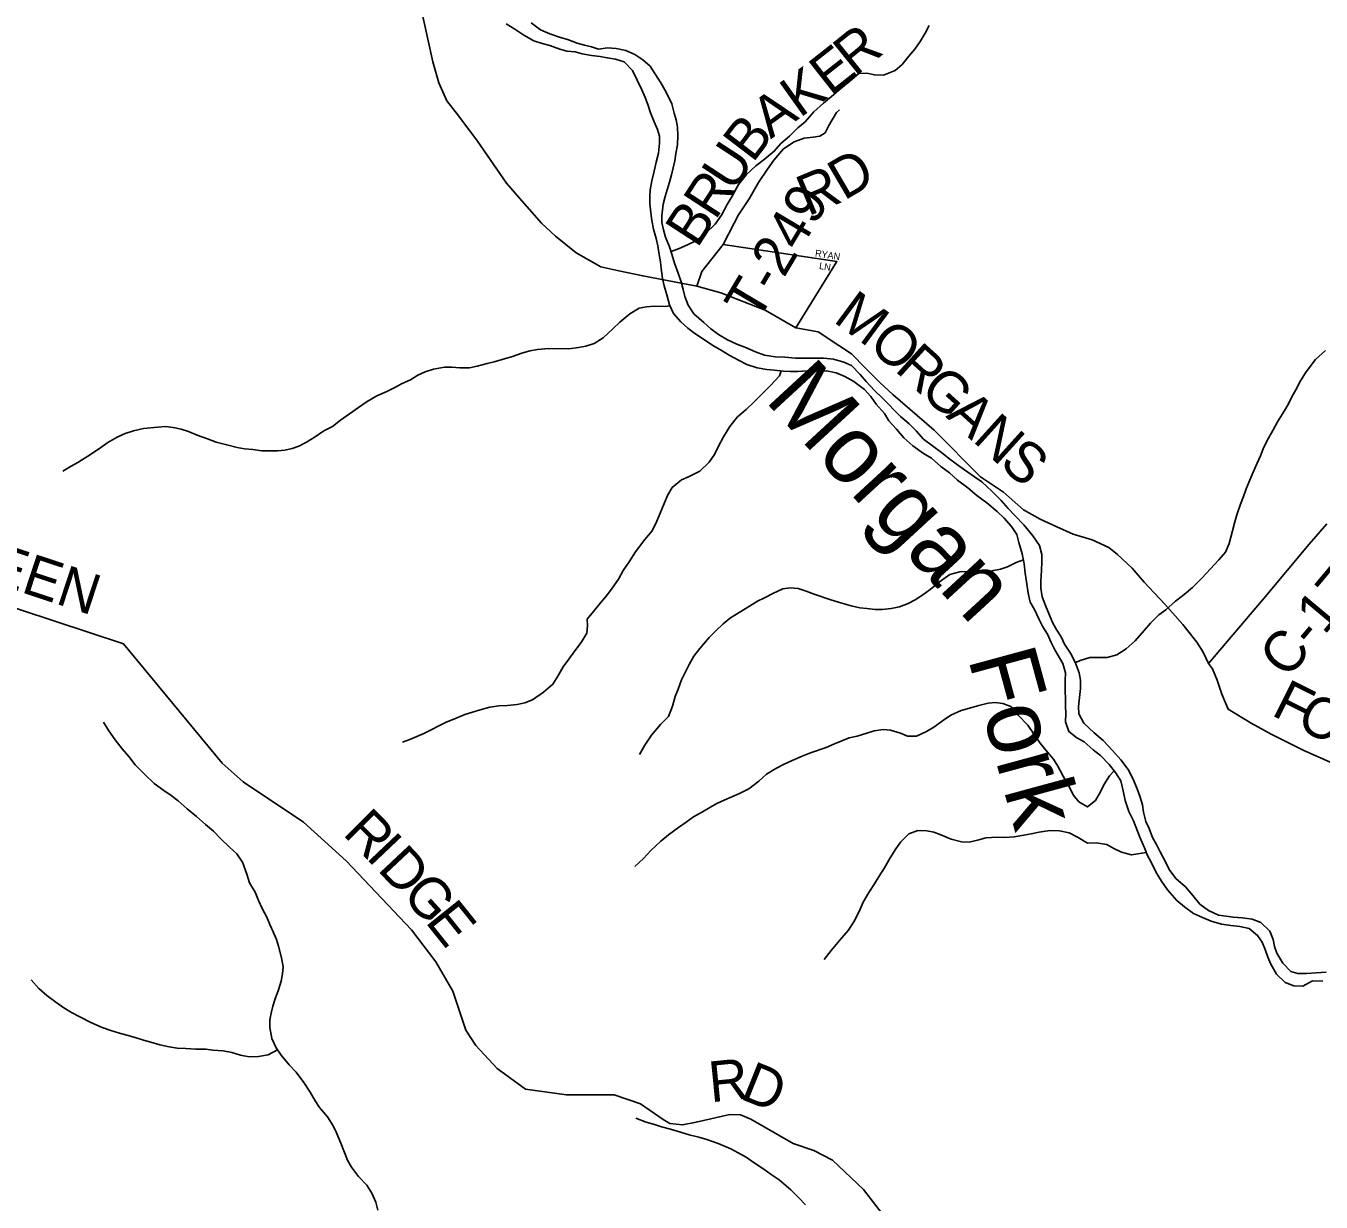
# Model space of a CAD drawing. Extents: x 1578669 to 1989827, y 208020 to 553079.
# Drawn here: x 1767882 to 1777435, y 401117 to 409792 of the extents above; entities that cross this region are included whole.
import ezdxf

# ---------------------------------------------------------------- set-up
doc = ezdxf.new("R2010")
doc.units = 0
for name, color, linetype in [('GM_X_County_Road', 7, 'Continuous'), ('GM_X_County_Road_Text', 7, 'Continuous'), ('GM_X_Minor_River', 7, 'Continuous'), ('GM_X_Minor_River_Text', 7, 'Continuous'), ('GM_X_Township_Road', 7, 'Continuous'), ('GM_X_Township_Road_Text', 7, 'Continuous'), ('GM_X_Township_Subdivision', 7, 'Continuous'), ('GM_X_Township_Subdivision_Text', 7, 'Continuous')]:
    doc.layers.add(name, color=color, linetype=linetype)

msp = doc.modelspace()

# ---------------------------------------------------------------- linework, layer by layer
at = {"layer": 'GM_X_County_Road'}
for points in [[(1777541.9, 404343.4), (1777306.9, 404446.4), (1777066, 404567.6), (1776918.9, 404649.6), (1776749.9, 404751.8), (1776703, 404862.7), (1776668.1, 404965.5), (1776633, 405050.2), (1776605.4, 405088.6), (1776566.3, 405173.4), (1776519.1, 405246.1), (1776414.4, 405375.8), (1776281.9, 405525.8), (1776129.6, 405688.1), (1776040.7, 405791.4), (1775933.7, 405893), (1775870.2, 405943.9), (1775746.8, 406001.5), (1775607.1, 406043.2), (1775485.7, 406096.8), (1775364.2, 406154.4), (1775240.9, 406222), (1775092.2, 406352.1), (1774923.4, 406466.4), (1774580.9, 406809.5), (1774275.6, 407073.9), (1774182.5, 407159.2), (1774075.6, 407266.8), (1773970.7, 407372.3), (1773879.3, 407435.6), (1773726.3, 407535.6), (1773560.7, 407565.8), (1773333.9, 407694.6), (1773007.1, 407822.7), (1772831.8, 407873.1), (1772432.2, 407947.6), (1772256.5, 407985.8), (1772122.7, 408015.4), (1771941.7, 408117.8), (1771789, 408241.9), (1771686, 408337.4), (1771521.9, 408519.9), (1771427, 408631.4), (1771212.3, 408940.8), (1771074.2, 409125), (1770987.3, 409238.4), (1770928.8, 409371.6), (1770884.4, 409526.6), (1770766.1, 410063.7)], [(1776605.4, 405088.6), (1777010.8, 405565.6), (1777347.3, 405969.2), (1777477, 406118.2)], [(1766567.4, 405904.3), (1768602.1, 405234.6), (1769330.8, 404353), (1769483.5, 404216.1), (1769929.6, 403920.1), (1770244.4, 403634.6), (1770726.1, 403123.8), (1770905.2, 402888.5), (1771032.1, 402672.4), (1771126.3, 402385.7), (1771199.5, 402271.2), (1771358.8, 402102.7), (1771566.8, 401950), (1771870.6, 401907.8), (1772222.2, 401908.5), (1772414.3, 401841), (1772583.3, 401727), (1772632, 401695.8), (1772725.2, 401686), (1772825.3, 401705.7), (1773073.6, 401762.2), (1773152.2, 401759.7), (1773228.8, 401729.6), (1773542.3, 401550.2), (1773693.7, 401497.3), (1773832.6, 401425.6), (1774060.7, 401209), (1774332.4, 400854.7)]]:
    msp.add_lwpolyline(points, dxfattribs=at)
at = {"layer": 'GM_X_Minor_River'}
for points in [[(1771424.1, 409807.3), (1771487.9, 409767), (1771553.7, 409722.7), (1771627.5, 409682.4), (1771689.3, 409662.2), (1771747.2, 409646), (1771819.1, 409619.7), (1771871, 409605.5), (1771932.9, 409599.3), (1771984.8, 409585.1), (1772054.7, 409572.9), (1772116.6, 409564.7), (1772170.6, 409556.5), (1772230.5, 409546.3), (1772294.4, 409526), (1772356.1, 409461.7), (1772391.8, 409391.4), (1772425.6, 409319.2), (1772449.3, 409263), (1772469.1, 409210.8), (1772488.9, 409150.6), (1772516.7, 409084.4), (1772540.5, 409028.2), (1772554.3, 408978), (1772556.1, 408925.9), (1772547.9, 408853.8), (1772531.7, 408787.7), (1772515.5, 408719.6), (1772499.2, 408649.5), (1772487, 408581.4), (1772484.9, 408531.3), (1772484.7, 408479.2), (1772490.5, 408413), (1772498.3, 408356.9), (1772510, 408292.7), (1772529.8, 408222.5), (1772543.6, 408170.3), (1772553.4, 408106.1), (1772563.2, 408052), (1772567, 408001.9), (1772576.8, 407929.7), (1772588.6, 407875.5), (1772608.3, 407807.3), (1772630.1, 407735.1), (1772657.8, 407670.9), (1772711.6, 407608.6), (1772765.4, 407562.3), (1772817.2, 407522.1), (1772894.9, 407471.7), (1772948.8, 407435.5), (1773004.6, 407403.2), (1773070.4, 407363), (1773144.2, 407322.6), (1773200.1, 407294.4), (1773275.9, 407270.1), (1773347.8, 407257.9), (1773401.8, 407251.7), (1773469.7, 407245.5), (1773521.6, 407243.3), (1773575.6, 407243.1), (1773645.5, 407246.9), (1773713.5, 407244.7), (1773787.4, 407248.5), (1773859.3, 407232.2), (1773923.1, 407206), (1773989, 407167.7), (1774066.7, 407109.3), (1774114.5, 407059.1), (1774152.3, 407000.8), (1774214, 406932.5), (1774247.8, 406878.3), (1774303.5, 406818), (1774357.2, 406753.7), (1774425, 406693.3), (1774502.7, 406639), (1774562.6, 406602.7), (1774630.3, 406542.4), (1774694.1, 406494.1), (1774753.9, 406441.8), (1774829.6, 406385.4), (1774895.3, 406327.1), (1774969.1, 406274.7), (1775046.8, 406210.3), (1775098.6, 406160.1), (1775152.4, 406099.8), (1775190.1, 406039.5), (1775205.9, 405981.4), (1775229.6, 405899.1), (1775245.4, 405824.9), (1775253.1, 405754.7)], [(1775431.9, 405445.5), (1775402.2, 405515.7), (1775378.4, 405581.9), (1775368.7, 405644.1), (1775368.8, 405696.2), (1775373.1, 405774.4), (1775375.3, 405838.5), (1775375.5, 405892.6), (1775357.7, 405958.8), (1775310, 406031.1), (1775242.3, 406111.5), (1775176.6, 406179.9), (1775126.8, 406232.1), (1775075.1, 406290.4), (1775005.4, 406360.8), (1774933.7, 406429.2), (1774877.8, 406465.4), (1774804.1, 406517.8), (1774752.2, 406554), (1774686.5, 406604.3), (1774634.6, 406644.6), (1774568.9, 406694.9), (1774503.1, 406743.2), (1774447.3, 406805.5), (1774397.6, 406855.8), (1774333.8, 406910.1), (1774200.4, 407044.8), (1774140.6, 407103.1), (1774078.9, 407169.4), (1774035.1, 407219.7), (1773971.4, 407286), (1773915.5, 407312.2), (1773839.6, 407332.5), (1773765.7, 407340.8), (1773557.9, 407341.4), (1773480, 407347.7), (1773408.1, 407351.9), (1773330.2, 407362.1), (1773262.3, 407388.4), (1773184.5, 407422.7), (1773126.6, 407445), (1773056.8, 407477.2), (1772991, 407515.5), (1772933.2, 407557.8), (1772881.4, 407604), (1772809.7, 407668.4), (1772765.9, 407730.7), (1772742.2, 407796.9), (1772730.3, 407847), (1772714.6, 407905.2), (1772692.8, 407967.4), (1772667.1, 408041.7), (1772647.3, 408107.9), (1772629.5, 408162), (1772599.8, 408234.3), (1772584, 408286.5), (1772572.1, 408340.6), (1772572.3, 408390.7), (1772582.6, 408476.9), (1772596.8, 408532.9), (1772610.9, 408583), (1772629.1, 408639.1), (1772643.3, 408693.1), (1772655.4, 408745.2), (1772667.6, 408795.3), (1772675.8, 408849.4), (1772688, 408913.5), (1772690.2, 408979.6), (1772688.4, 409045.8), (1772678.6, 409097.9), (1772664.8, 409148.1), (1772647, 409216.3), (1772605.3, 409302.6), (1772565.6, 409370.9), (1772521.9, 409441.1), (1772486.1, 409493.4), (1772432.3, 409541.6), (1772374.5, 409579.9), (1772306.6, 409610.2), (1772236.7, 409624.4), (1772170.8, 409628.6), (1772104.8, 409620.8), (1772052.9, 409637), (1772001, 409649.2), (1771949.1, 409663.4), (1771883.3, 409687.6), (1771817.4, 409707.9), (1771745.5, 409734.2), (1771677.7, 409762.4), (1771607.9, 409814.8)], [(1772640.7, 408127.8), (1772699.4, 408149.8), (1772761.4, 408177.7), (1772829.5, 408209.5), (1772895.6, 408261.4), (1772965.8, 408329.4), (1773011.9, 408395.4), (1773054.2, 408473.4), (1773092.3, 408535.4), (1773138.6, 408621.5), (1773196.8, 408695.5), (1773264.9, 408759.4), (1773327, 408805.3), (1773401.2, 408867.2), (1773449.3, 408923.2), (1773513.4, 408977.1), (1773575.6, 409039), (1773629.7, 409083), (1773693.9, 409156.9), (1773766, 409220.9), (1773824.2, 409270.8), (1773892.3, 409328.7), (1773958.4, 409384.6), (1774026.5, 409440.5), (1774084.5, 409442.4), (1774140.4, 409430.2), (1774208.3, 409428), (1774292.4, 409463.8), (1774344.5, 409505.7), (1774394.6, 409567.7), (1774438.8, 409619.7), (1774476.9, 409675.7), (1774515.1, 409737.7), (1774543.3, 409793.7)], [(1772634, 407725.9), (1772594, 407721.2), (1772516.1, 407723.4), (1772460.2, 407719.6), (1772404.2, 407709.7), (1772336.1, 407667.9), (1772261.9, 407606), (1772211.8, 407558), (1772139.7, 407492.1), (1772073.6, 407450.2), (1772011.6, 407430.3), (1771957.6, 407418.5), (1771887.6, 407410.7), (1771737.7, 407411.1), (1771655.8, 407405.4), (1771597.8, 407395.5), (1771539.8, 407377.7), (1771471.8, 407353.8), (1771395.8, 407330), (1771335.8, 407314.2), (1771283.8, 407302.3), (1771209.8, 407282.5), (1771153.8, 407270.7), (1771081.8, 407270.9), (1771023.9, 407275.1), (1770970, 407275.2), (1770888, 407259.5), (1770827.9, 407239.6), (1770773.9, 407215.7), (1770719.8, 407181.8), (1770657.8, 407154), (1770603.8, 407124.1), (1770543.7, 407096.2), (1770469.7, 407062.3), (1770399.6, 407022.5), (1770335.5, 406976.6), (1770269.4, 406930.7), (1770203.3, 406882.8), (1770143.2, 406836.9), (1770079.1, 406805), (1770015, 406761.1), (1769950.9, 406721.2), (1769894.9, 406691.3), (1769844.9, 406675.5), (1769790.9, 406663.6), (1769738.9, 406657.8), (1769623, 406658.1), (1769557.1, 406666.4), (1769495.1, 406672.6), (1769441.2, 406682.8), (1769363.4, 406701.1), (1769285.5, 406721.3), (1769221.6, 406745.6), (1769145.8, 406773.9), (1769081.9, 406800.2), (1769028, 406818.4), (1768968.1, 406830.6), (1768912.2, 406836.8), (1768856.2, 406833), (1768748.3, 406821.3), (1768676.3, 406805.5), (1768614.2, 406785.6), (1768556.2, 406757.8), (1768486.1, 406717.9), (1768434, 406682), (1768365.9, 406636.1), (1768265.8, 406572.3), (1768215.7, 406544.4), (1768153.7, 406506.5)], [(1775622.4, 405093.3), (1775658.6, 405112), (1775730.6, 405133.9), (1775858.5, 405133.5), (1775928.5, 405153.3), (1775996.6, 405197.2), (1776064.8, 405257.1), (1776131, 405333), (1776177.1, 405387), (1776239.3, 405447), (1776289.3, 405484.9), (1776361.5, 405548.8), (1776425.6, 405598.7), (1776485.7, 405650.6), (1776555.9, 405718.5), (1776620.1, 405786.5), (1776680.3, 405854.4), (1776730.4, 405910.4), (1776756.6, 405974.5), (1776782.9, 406068.6), (1776799.1, 406132.7), (1776813.2, 406184.7), (1776839.5, 406264.8), (1776863.7, 406320.9), (1776881.8, 406376.9), (1776920.1, 406465), (1776950.3, 406539.1), (1776988.6, 406621.1), (1777006.7, 406673.2), (1777036.9, 406733.2), (1777079.1, 406807.2), (1777113.3, 406871.3), (1777163.5, 406951.3), (1777193.7, 407005.3), (1777219.8, 407055.3), (1777250, 407107.4), (1777284.2, 407173.4), (1777324.4, 407241.4), (1777394.6, 407331.4), (1777466.8, 407397.3)], [(1773452.9, 407247), (1773441.6, 407211.5), (1773373.4, 407139.5), (1773303.2, 407067.6), (1773251.1, 407017.6), (1773195, 406961.7), (1773130.8, 406907.8), (1773074.7, 406837.8), (1773026.4, 406759.8), (1772990.2, 406691.7), (1772962.1, 406631.7), (1772921.9, 406573.7), (1772851.7, 406507.8), (1772773.7, 406467.9), (1772717.7, 406444), (1772649.5, 406386.1), (1772617.4, 406334.1), (1772589.2, 406268), (1772561, 406198), (1772534.8, 406139.9), (1772500.6, 406067.9), (1772448.4, 406003.9), (1772378.2, 405911.9), (1772332, 405839.9), (1772287.8, 405773.9), (1772253.6, 405711.9), (1772207.4, 405643.9), (1772165.3, 405587.9), (1772119.1, 405535.9), (1772069, 405471.9), (1772022.8, 405415.9), (1772024.6, 405365.8), (1772020.5, 405311.7), (1771978.3, 405243.7), (1771932.1, 405183.7), (1771885.9, 405121.7), (1771845.8, 405065.7), (1771805.6, 404995.7), (1771769.4, 404935.7), (1771699.3, 404877.8), (1771619.2, 404821.9), (1771563.1, 404800), (1771505.1, 404786.2), (1771433.2, 404780.4), (1771371.2, 404776.6), (1771305.2, 404766.8), (1771233.2, 404747), (1771175.2, 404731.1), (1771119.2, 404713.2), (1771039.2, 404677.4), (1770983.1, 404657.5), (1770927.1, 404629.6), (1770871, 404599.8), (1770817, 404573.9), (1770765, 404550), (1770714.9, 404528.1), (1770660.9, 404508.2)], [(1775239.1, 405854.5), (1775185.4, 405833.1), (1775121.4, 405801.2), (1775071.4, 405785.3), (1775007.4, 405773.5), (1774953.4, 405769.7), (1774897.5, 405767.8), (1774839.5, 405768), (1774771.6, 405766.2), (1774695.6, 405746.4), (1774621.5, 405690.5), (1774551.3, 405634.6), (1774497.2, 405594.7), (1774441.2, 405558.8), (1774389.1, 405530.9), (1774325.1, 405507.1), (1774265.1, 405495.2), (1774197.1, 405487.4), (1774145.2, 405487.6), (1774085.3, 405493.8), (1774033.3, 405499.9), (1773969.4, 405514.2), (1773883.6, 405538.5), (1773811.7, 405560.8), (1773696, 405601.2), (1773638.1, 405623.4), (1773578.2, 405641.6), (1773518.3, 405647.8), (1773464.3, 405640), (1773392.3, 405606.1), (1773330.2, 405572.3), (1773278.2, 405548.4), (1773218.1, 405512.5), (1773077.9, 405424.7), (1773023.8, 405380.8), (1772973.7, 405332.8), (1772921.6, 405280.9), (1772853.4, 405200.9), (1772809.2, 405142.9), (1772775, 405080.9), (1772718.7, 404968.8), (1772692.5, 404900.8), (1772670.3, 404846.7), (1772652.1, 404774.6), (1772621.9, 404698.5), (1772563.7, 404638.6), (1772497.5, 404560.6), (1772447.3, 404486.6), (1772409.1, 404418.6)], [(1775253.1, 405754.7), (1775262.9, 405692.5), (1775274.6, 405608.3), (1775288.4, 405542.1), (1775320.2, 405487.9), (1775353.9, 405417.7), (1775383.7, 405359.5), (1775417.5, 405305.2), (1775443.3, 405245), (1775471, 405188.8), (1775530.7, 405088.4), (1775550.4, 405020.2), (1775548.2, 404960.1), (1775548, 404885.9), (1775549.8, 404831.8), (1775549.6, 404777.6), (1775551.4, 404719.5), (1775549.2, 404659.4), (1775574.9, 404587.2), (1775634.7, 404540.9), (1775688.6, 404510.6), (1775754.3, 404452.3), (1775808.2, 404410), (1775871.9, 404343.7), (1775917.6, 404285.4), (1775957.4, 404223.2), (1775975.1, 404149), (1775988.9, 404078.8), (1776016.6, 403996.5), (1776050.3, 403928.2), (1776097.9, 403807.8), (1776131.6, 403729.5), (1776155.4, 403673.3), (1776181.2, 403623.1), (1776218.9, 403548.9), (1776258.7, 403484.6), (1776302.4, 403420.3), (1776372.1, 403341.9), (1776427.9, 403293.6), (1776493.7, 403245.3), (1776559.5, 403215.1), (1776623.4, 403188.8), (1776701.2, 403166.5), (1776769.2, 403156.3), (1776835.1, 403150), (1776905, 403133.8), (1776966.8, 403083.5), (1777000.6, 403033.2), (1777022.4, 402979.1), (1777042.2, 402922.9), (1777064, 402870.7), (1777105.7, 402798.4), (1777169.4, 402736.1), (1777233.3, 402711.8), (1777301.2, 402709.6), (1777371.3, 402747.5), (1777447.2, 402745.2)], [(1777473.4, 402813.3), (1777399.5, 402807.5), (1777327.5, 402801.7), (1777263.6, 402803.9), (1777211.7, 402818.1), (1777153.9, 402878.4), (1777108.2, 402952.7), (1777092.4, 403002.9), (1777080.6, 403053), (1777056.8, 403115.2), (1776991.1, 403179.6), (1776927.2, 403203.9), (1776855.3, 403214.1), (1776787.3, 403218.3), (1776735.4, 403224.5), (1776679.5, 403232.7), (1776605.7, 403267), (1776539.9, 403315.3), (1776490.1, 403377.6), (1776434.4, 403441.9), (1776362.7, 403504.3), (1776314.9, 403568.6), (1776285.1, 403630.8), (1776249.4, 403699.1), (1776221.6, 403753.3), (1776191.8, 403805.5), (1776166.1, 403871.7), (1776142.2, 403923.9), (1776124.5, 403992.1), (1776116.7, 404046.3), (1776098.9, 404110.5), (1776079.1, 404164.6), (1776047.4, 404240.9), (1776011.6, 404307.2), (1775957.9, 404377.5), (1775896.2, 404447.8), (1775828.5, 404520.2), (1775760.8, 404578.6), (1775685.1, 404649), (1775649.3, 404717.2), (1775645.5, 404771.3), (1775653.7, 404837.5), (1775659.9, 404905.6), (1775660.1, 404965.7), (1775650.3, 405019.9), (1775620.6, 405098.1), (1775586.9, 405164.4), (1775543.1, 405232.7), (1775517.3, 405284.9), (1775485.5, 405335.1), (1775457.7, 405387.3), (1775431.9, 405445.5)], [(1775908.1, 404297.6), (1775875.6, 404261.5), (1775833.4, 404193.5), (1775807.3, 404143.5), (1775771.1, 404079.4), (1775711, 404031.5), (1775649.1, 404069.8), (1775605.4, 404120), (1775579.6, 404178.2), (1775531.9, 404258.6), (1775494.2, 404330.8), (1775460.4, 404383.1), (1775416.6, 404435.3), (1775362.8, 404501.6), (1775313.1, 404574), (1775271.4, 404634.2), (1775201.7, 404708.6), (1775145.9, 404772.9), (1775088.1, 404795.1), (1775032.1, 404801.3), (1774980.1, 404795.5), (1774910.2, 404779.7), (1774860.1, 404765.8), (1774780.1, 404742), (1774704.1, 404708.1), (1774650, 404672.2), (1774577.9, 404620.3), (1774523.9, 404588.4), (1774451.8, 404552.6), (1774385.8, 404552.8), (1774334, 404575), (1774258.1, 404597.3), (1774204.2, 404601.5), (1774138.2, 404593.6), (1774084.2, 404575.8), (1774012.2, 404553.9), (1773954.2, 404540.1), (1773846.1, 404496.3), (1773784.1, 404470.5), (1773668.1, 404430.7), (1773608, 404404.9), (1773534, 404373), (1773476, 404347.2), (1773413.9, 404315.3), (1773345.8, 404273.4), (1773287.7, 404221.5), (1773213.6, 404163.6), (1773145.5, 404129.7), (1773033.4, 404082), (1772979.4, 404056.1), (1772927.4, 404028.2), (1772873.3, 403996.2), (1772807.2, 403958.4), (1772753.1, 403918.5), (1772695.1, 403878.5), (1772620.9, 403824.6), (1772564.8, 403778.7), (1772492.7, 403710.8), (1772436.5, 403650.8), (1772372.4, 403590.9)], [(1768755.7, 404273.7), (1768688, 404342.1), (1768642.2, 404402.4), (1768592.4, 404458.7), (1768540.7, 404527), (1768493, 404593.3), (1768455.2, 404655.5)], [(1770477.5, 401057.4), (1770463.7, 401117.5), (1770433.9, 401181.8), (1770396.2, 401242), (1770336.4, 401306.3), (1770284.7, 401374.7), (1770254.9, 401424.9), (1770233.1, 401483), (1770205.4, 401551.3), (1770173.6, 401627.5), (1770147.8, 401679.7), (1770106.1, 401746), (1770048.4, 401814.3), (1770014.6, 401864.6), (1769978.8, 401926.8), (1769933.1, 401999.1), (1769875.4, 402075.5), (1769823.6, 402129.7), (1769765.9, 402200.1), (1769728.1, 402254.3), (1769696.4, 402322.5), (1769680.7, 402404.8), (1769680.8, 402460.9), (1769691, 402511), (1769703.2, 402561), (1769721.3, 402617.1), (1769745.5, 402681.2), (1769765.7, 402747.2), (1769775.9, 402799.3), (1769780.1, 402851.4), (1769768.3, 402917.6), (1769744.6, 403003.9), (1769730.8, 403054), (1769705, 403110.2), (1769681.2, 403164.4), (1769659.4, 403218.6), (1769625.7, 403282.8), (1769597.9, 403341), (1769572.1, 403403.3), (1769532.4, 403471.5), (1769512.6, 403535.7), (1769478.9, 403624), (1769437.2, 403684.3), (1769383.4, 403734.6), (1769319.6, 403794.9), (1769265.9, 403853.2), (1769206.1, 403901.5), (1769140.3, 403959.8), (1769070.6, 404018.2), (1769004.8, 404076.5), (1768953, 404116.8), (1768899.2, 404153), (1768827.4, 404203.3), (1768755.7, 404273.7)], [(1776145.8, 403696), (1776037.5, 403677.7), (1775963.6, 403698), (1775905.8, 403724.2), (1775853.9, 403754.5), (1775776, 403766.7), (1775712.1, 403764.9), (1775642.3, 403805.2), (1775576.4, 403839.5), (1775504.6, 403855.8), (1775434.6, 403858), (1775354.6, 403844.2), (1775296.7, 403832.4), (1775242.7, 403822.5), (1775170.7, 403810.7), (1775100.7, 403804.9), (1775044.8, 403807.1), (1774962.8, 403803.4), (1774910.8, 403789.5), (1774838.8, 403771.7), (1774782.9, 403773.9), (1774707, 403794.1), (1774631.2, 403824.4), (1774579.3, 403844.6), (1774527.4, 403854.8), (1774461.5, 403857), (1774395.4, 403833.2), (1774335.3, 403773.2), (1774299.1, 403721.2), (1774257, 403655.2), (1774214.8, 403583.2), (1774176.6, 403521.2), (1774142.4, 403463.2), (1774100.2, 403401.2), (1774058, 403329.1), (1774027.8, 403259.1), (1773989.6, 403183), (1773947.4, 403121), (1773883.2, 403045.1), (1773821.1, 402973.1), (1773770.9, 402907.1)], [(1769738.8, 402238.9), (1769668, 402202.4), (1769598, 402190.6), (1769530.1, 402188.8), (1769466.1, 402201), (1769400.3, 402219.3), (1769336.4, 402231.5), (1769260.4, 402237.7), (1769208.5, 402243.9), (1769134.6, 402244.2), (1769062.6, 402250.4), (1768998.7, 402252.6), (1768938.8, 402262.8), (1768868.9, 402277.1), (1768803, 402295.3), (1768749.1, 402311.5), (1768689.2, 402329.8), (1768627.3, 402348), (1768573.4, 402362.2), (1768509.5, 402382.4), (1768443.7, 402404.7), (1768361.9, 402441), (1768280.1, 402483.4), (1768218.2, 402515.7), (1768162.4, 402549.9), (1768102.6, 402590.2), (1768036.8, 402640.5), (1767977, 402692.8), (1767921.3, 402755.1)], [(1773632.9, 401095.6), (1773583.1, 401147.9), (1773523.4, 401208.2), (1773437.7, 401280.6), (1773379.9, 401320.9), (1773326.1, 401359.2), (1773254.3, 401407.5), (1773194.5, 401447.8), (1773136.6, 401480), (1773080.8, 401510.2), (1772987, 401548.6), (1772905.2, 401578.9), (1772845.3, 401595.2), (1772775.4, 401613.4), (1772711.5, 401631.6), (1772635.7, 401653.9), (1772569.8, 401672.2), (1772517.9, 401688.4), (1772458, 401706.6), (1772380.1, 401734.9)]]:
    msp.add_lwpolyline(points, dxfattribs=at)
at = {"layer": 'GM_X_Township_Road'}
for points in [[(1773105.9, 408336.3), (1773137.3, 408397.2), (1773216.7, 408516.8), (1773286, 408636.4), (1773353, 408734), (1773399.8, 408801.7), (1773470.7, 408885.1), (1773549.3, 408936.5), (1773621.6, 408963.7), (1773687.8, 408971), (1773737.9, 408978.4), (1773778.1, 409004.1), (1773804.7, 409056), (1773861.2, 409151.9), (1773882, 409171.5)], [(1772831.8, 407873.1), (1772868.7, 407980.8), (1773024.9, 408179), (1773105.5, 408335.6), (1773105.9, 408336.3)]]:
    msp.add_lwpolyline(points, dxfattribs=at)
at = {"layer": 'GM_X_Township_Subdivision'}
msp.add_lwpolyline([(1773560.7, 407565.8), (1773864, 408053.9), (1773024.9, 408179)], dxfattribs=at)

# ---------------------------------------------------------------- texts
at = {"layer": 'GM_X_County_Road_Text'}
for s, rotation, p in [('M', 323.58261, (1773828.6, 407614.5)), ('O', 318.7195, (1774085.4, 407425.5)), ('R', 317.88804, (1774282.9, 407252.1)), ('G', 317.88093, (1774465.7, 407086.8)), ('A', 317.87979, (1774661.5, 406909.8)), ('N', 317.88244, (1774857.4, 406732.7)), ('S', 317.88388, (1775053.2, 406555.7)), ('GREEN', 341.76099, (1767012.4, 405889.4)), ('C-17', 50.10652, (1777187.3, 404967.8)), ('F', 333.32233, (1777059.5, 404712.8)), ('O', 333.31766, (1777240.3, 404621.9)), ('R', 314.99173, (1770210.9, 403830.6)), ('I', 313.50404, (1770383.7, 403657.9)), ('D', 313.21983, (1770468.2, 403568.8)), ('G', 311.94362, (1770647.8, 403377.7)), ('E', 308.65647, (1770821.4, 403184.8)), ('R', 5.69583, (1772933, 401852.6)), ('D', 338.01258, (1773140.6, 401882.4))]:
    msp.add_text(s, height=300, rotation=rotation, dxfattribs=at).set_placement(p)
at = {"layer": 'GM_X_Minor_River_Text'}
for s, height, rotation, p in [('Morgan', 499.96, 312.66191, (1773323.9, 407031.4)), ('Fork', 500.03, 285.21332, (1774829, 405129.1))]:
    msp.add_text(s, height=height, rotation=rotation, dxfattribs=at).set_placement(p)
at = {"layer": 'GM_X_Township_Road_Text'}
for s, rotation, p in [('R', 38.90888, (1773995.9, 409412.5)), ('E', 38.18151, (1773816.2, 409271.2)), ('K', 35.51099, (1773589.1, 409108.7)), ('A', 35.90015, (1773375.7, 408954.2)), ('B', 52.66485, (1773242.9, 408774.5)), ('U', 56.8141, (1773101.7, 408558.2)), ('D', 30.3838, (1773916, 408499.9)), ('R', 56.9213, (1772967.3, 408351.9)), ('R', 22.73275, (1773650.3, 408385.5)), ('T-249', 59.26104, (1773279, 407602.1)), ('B', 56.91722, (1772832.8, 408145.4))]:
    msp.add_text(s, height=300, rotation=rotation, dxfattribs=at).set_placement(p)
at = {"layer": 'GM_X_Township_Subdivision_Text'}
for s, rotation, p in [('RYAN', 351.02619, (1773700.1, 408092)), ('LN', 350.54359, (1773730.2, 407999.4))]:
    msp.add_text(s, height=50, rotation=rotation, dxfattribs=at).set_placement(p)

doc.saveas('drawing.dxf')
